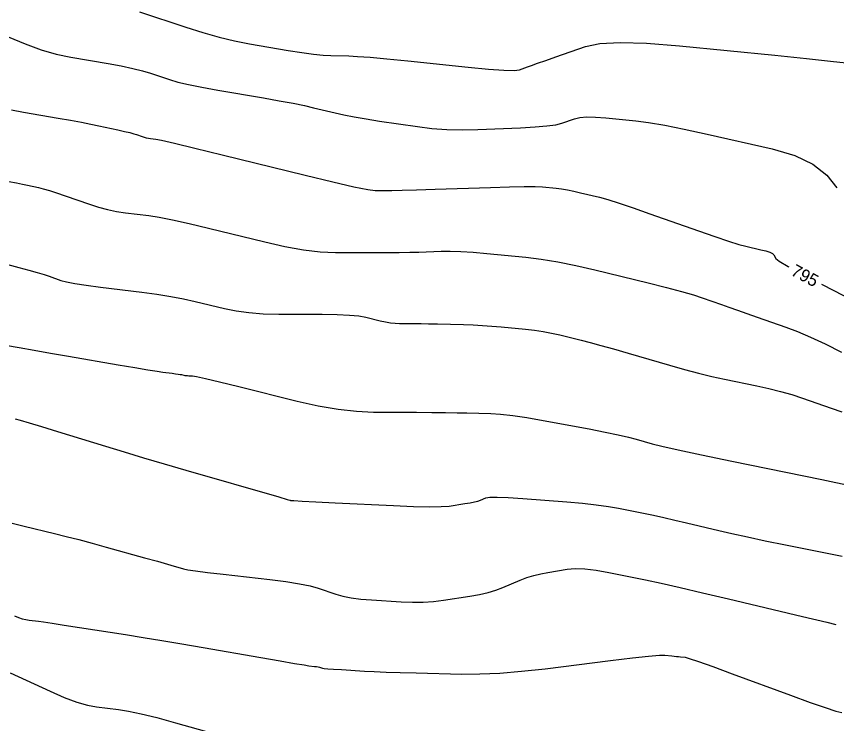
# Model space of a CAD drawing. Extents: x 2082232 to 2083549, y 592624 to 593832.
# Drawn here: x 2082281.15 to 2082327.71, y 593026.54 to 593066.69 of the extents above; entities that cross this region are included whole.
import ezdxf

# ---------------------------------------------------------------- set-up
doc = ezdxf.new("R2010")
doc.units = 0
doc.layers.add('DT_X_Contour_Major', color=7, linetype='Continuous')
doc.layers.add('DT_X_Contour_Minor', color=7, linetype='Continuous')

msp = doc.modelspace()

# ---------------------------------------------------------------- linework, layer by layer
at = {"layer": 'DT_X_Contour_Major'}
for points in [[(2082280.863, 593061.384), (2082281.552, 593061.256), (2082283.525, 593060.92), (2082284.223, 593060.799), (2082284.839, 593060.687), (2082285.371, 593060.584), (2082285.82, 593060.49), (2082286.908, 593060.251), (2082287.279, 593060.167), (2082287.579, 593060.095), (2082287.807, 593060.035), (2082287.963, 593059.987), (2082288.284, 593059.876), (2082288.404, 593059.837), (2082288.522, 593059.806), (2082288.64, 593059.781), (2082288.756, 593059.764), (2082289.064, 593059.726), (2082289.386, 593059.66), (2082290.121, 593059.488), (2082291.268, 593059.212), (2082292.827, 593058.83), (2082297.536, 593057.673), (2082299.109, 593057.293), (2082300.297, 593057.021), (2082301.1, 593056.858), (2082301.518, 593056.803), (2082302.119, 593056.801), (2082302.463, 593056.805), (2082303.045, 593056.82), (2082303.866, 593056.845), (2082304.924, 593056.881), (2082308.065, 593056.989), (2082309.132, 593057.021), (2082309.978, 593057.036), (2082310.603, 593057.034), (2082311.007, 593057.014), (2082311.79, 593056.939), (2082312.097, 593056.902), (2082312.431, 593056.847), (2082312.791, 593056.775), (2082313.177, 593056.686), (2082314.244, 593056.423), (2082314.723, 593056.291), (2082315.36, 593056.092), (2082316.155, 593055.827), (2082317.108, 593055.494), (2082319.861, 593054.519), (2082320.804, 593054.19), (2082321.569, 593053.934), (2082322.156, 593053.751), (2082322.564, 593053.642), (2082323.416, 593053.449), (2082323.7, 593053.376), (2082323.916, 593053.301), (2082324.063, 593053.226), (2082324.14, 593053.149), (2082324.255, 593052.941), (2082324.454, 593052.79), (2082324.966, 593052.491), (2082325.005, 593052.47)], [(2082326.86, 593051.486), (2082326.926, 593051.451), (2082330.373, 593049.672)], [(2082280.911, 593037.923), (2082281.594, 593037.745), (2082283.312, 593037.331), (2082283.979, 593037.167), (2082284.689, 593036.984), (2082285.444, 593036.784), (2082286.242, 593036.565), (2082288.429, 593035.958), (2082289.162, 593035.754), (2082289.721, 593035.597), (2082290.105, 593035.488), (2082290.315, 593035.426), (2082290.642, 593035.324), (2082290.874, 593035.276), (2082291.324, 593035.209), (2082291.992, 593035.124), (2082292.878, 593035.019), (2082295.532, 593034.716), (2082296.449, 593034.601), (2082297.212, 593034.482), (2082297.82, 593034.36), (2082298.274, 593034.235), (2082299.276, 593033.895), (2082299.685, 593033.779), (2082300.159, 593033.685), (2082300.698, 593033.612), (2082301.302, 593033.561), (2082302.999, 593033.455), (2082303.627, 593033.431), (2082304.235, 593033.439), (2082304.825, 593033.477), (2082305.395, 593033.547), (2082306.892, 593033.776), (2082307.429, 593033.871), (2082307.92, 593033.983), (2082308.363, 593034.114), (2082308.759, 593034.262), (2082309.753, 593034.681), (2082310.131, 593034.827), (2082310.517, 593034.95), (2082310.913, 593035.05), (2082311.318, 593035.127), (2082312.409, 593035.302), (2082312.865, 593035.34), (2082313.413, 593035.321), (2082314.054, 593035.247), (2082314.787, 593035.117), (2082316.866, 593034.695), (2082317.745, 593034.509), (2082318.823, 593034.269), (2082320.099, 593033.974), (2082321.575, 593033.625), (2082325.775, 593032.621), (2082327.156, 593032.291), (2082327.671, 593032.167)]]:
    msp.add_lwpolyline(points, dxfattribs=at)
at = {"layer": 'DT_X_Contour_Minor'}
for points in [[(2082288.139, 593066.96), (2082290.764, 593066.079), (2082291.729, 593065.773), (2082292.653, 593065.513), (2082293.537, 593065.301), (2082294.381, 593065.137), (2082296.579, 593064.76), (2082297.348, 593064.636), (2082298.007, 593064.546), (2082298.556, 593064.489), (2082298.994, 593064.466), (2082300.016, 593064.45), (2082300.512, 593064.427), (2082301.235, 593064.373), (2082302.184, 593064.287), (2082303.36, 593064.168), (2082306.797, 593063.808), (2082307.946, 593063.698), (2082308.815, 593063.637), (2082309.404, 593063.626), (2082309.714, 593063.665), (2082310.166, 593063.833), (2082310.394, 593063.916), (2082310.736, 593064.038), (2082311.195, 593064.2), (2082311.768, 593064.401), (2082313.452, 593064.989), (2082314.259, 593065.157), (2082315.416, 593065.219), (2082316.923, 593065.175), (2082318.781, 593065.026), (2082324.202, 593064.485), (2082326.007, 593064.302), (2082327.354, 593064.158), (2082328.243, 593064.053)], [(2082280.681, 593065.537), (2082281.638, 593065.13), (2082282.549, 593064.801), (2082283.414, 593064.549), (2082284.232, 593064.375), (2082286.353, 593064.014), (2082287.1, 593063.879), (2082287.749, 593063.744), (2082288.3, 593063.608), (2082288.754, 593063.472), (2082289.834, 593063.11), (2082290.309, 593062.97), (2082290.926, 593062.823), (2082291.684, 593062.669), (2082292.583, 593062.506), (2082295.169, 593062.064), (2082296.074, 593061.905), (2082296.852, 593061.759), (2082297.501, 593061.628), (2082298.022, 593061.511), (2082299.24, 593061.216), (2082299.741, 593061.104), (2082300.329, 593060.99), (2082301.004, 593060.874), (2082301.766, 593060.755), (2082303.915, 593060.435), (2082304.734, 593060.335), (2082305.578, 593060.274), (2082306.449, 593060.253), (2082307.345, 593060.271), (2082309.769, 593060.371), (2082310.597, 593060.415), (2082311.264, 593060.473), (2082311.771, 593060.545), (2082312.116, 593060.631), (2082312.821, 593060.877), (2082313.132, 593060.95), (2082313.535, 593060.984), (2082314.03, 593060.979), (2082314.617, 593060.936), (2082316.306, 593060.767), (2082317.034, 593060.673), (2082317.951, 593060.515), (2082319.057, 593060.294), (2082320.353, 593060.01), (2082324.059, 593059.169), (2082325.331, 593058.794), (2082326.364, 593058.3), (2082327.159, 593057.686), (2082327.717, 593056.953)], [(2082280.724, 593057.312), (2082281.149, 593057.237), (2082281.498, 593057.171), (2082281.772, 593057.114), (2082282.404, 593056.976), (2082282.676, 593056.907), (2082283.018, 593056.807), (2082283.431, 593056.674), (2082283.915, 593056.509), (2082285.3, 593056.027), (2082285.816, 593055.861), (2082286.328, 593055.725), (2082286.835, 593055.619), (2082287.337, 593055.543), (2082288.669, 593055.381), (2082289.255, 593055.291), (2082290.015, 593055.143), (2082290.949, 593054.937), (2082292.058, 593054.672), (2082295.244, 593053.889), (2082296.392, 593053.631), (2082297.444, 593053.447), (2082298.4, 593053.335), (2082299.261, 593053.296), (2082301.428, 593053.288), (2082302.199, 593053.288), (2082302.883, 593053.293), (2082303.483, 593053.302), (2082303.997, 593053.316), (2082305.253, 593053.359), (2082305.769, 593053.363), (2082306.375, 593053.344), (2082307.071, 593053.3), (2082307.856, 593053.232), (2082310.07, 593053.019), (2082310.937, 593052.915), (2082311.88, 593052.76), (2082312.898, 593052.556), (2082313.99, 593052.303), (2082317.004, 593051.56), (2082318.044, 593051.298), (2082318.903, 593051.07), (2082319.582, 593050.876), (2082320.079, 593050.714), (2082321.166, 593050.33), (2082321.598, 593050.177), (2082322.082, 593050.008), (2082322.616, 593049.822), (2082323.201, 593049.619), (2082324.829, 593049.056), (2082325.484, 593048.809), (2082326.229, 593048.489), (2082327.064, 593048.097), (2082327.99, 593047.632)], [(2082279.652, 593052.876), (2082281.292, 593052.436), (2082281.86, 593052.281), (2082282.336, 593052.146), (2082282.719, 593052.031), (2082283.01, 593051.936), (2082283.662, 593051.708), (2082283.987, 593051.62), (2082284.471, 593051.527), (2082285.114, 593051.427), (2082285.918, 593051.323), (2082288.273, 593051.036), (2082289.124, 593050.923), (2082289.91, 593050.798), (2082290.631, 593050.662), (2082291.288, 593050.514), (2082292.953, 593050.105), (2082293.615, 593049.97), (2082294.352, 593049.873), (2082295.164, 593049.814), (2082296.05, 593049.792), (2082298.514, 593049.783), (2082299.361, 593049.771), (2082300.054, 593049.74), (2082300.594, 593049.691), (2082300.981, 593049.623), (2082301.807, 593049.418), (2082302.107, 593049.351), (2082302.387, 593049.302), (2082302.647, 593049.273), (2082302.887, 593049.262), (2082303.5, 593049.259), (2082303.77, 593049.256), (2082304.12, 593049.25), (2082304.55, 593049.242), (2082305.06, 593049.23), (2082306.527, 593049.195), (2082307.073, 593049.178), (2082307.611, 593049.151), (2082308.141, 593049.115), (2082308.663, 593049.069), (2082310.045, 593048.937), (2082310.556, 593048.879), (2082311.051, 593048.806), (2082311.53, 593048.717), (2082311.993, 593048.613), (2082313.207, 593048.313), (2082313.715, 593048.183), (2082314.329, 593048.017), (2082315.049, 593047.815), (2082315.873, 593047.577), (2082318.214, 593046.894), (2082319.068, 593046.652), (2082319.875, 593046.439), (2082320.634, 593046.255), (2082321.347, 593046.099), (2082323.184, 593045.722), (2082323.863, 593045.572), (2082324.522, 593045.404), (2082325.162, 593045.22), (2082325.781, 593045.018), (2082327.408, 593044.455), (2082328.006, 593044.238)], [(2082280.534, 593048.021), (2082281.304, 593047.887), (2082282.157, 593047.739), (2082283.092, 593047.577), (2082284.108, 593047.401), (2082286.927, 593046.915), (2082287.878, 593046.752), (2082288.616, 593046.628), (2082289.141, 593046.544), (2082289.453, 593046.499), (2082290, 593046.433), (2082290.187, 593046.409), (2082290.335, 593046.389), (2082290.446, 593046.371), (2082290.519, 593046.356), (2082290.662, 593046.321), (2082290.719, 593046.31), (2082290.783, 593046.301), (2082290.853, 593046.296), (2082290.929, 593046.294), (2082291.141, 593046.293), (2082291.366, 593046.255), (2082291.881, 593046.139), (2082292.686, 593045.946), (2082293.781, 593045.677), (2082297.088, 593044.855), (2082298.288, 593044.585), (2082299.409, 593044.391), (2082300.45, 593044.272), (2082301.411, 593044.23), (2082303.867, 593044.217), (2082304.736, 593044.211), (2082305.502, 593044.203), (2082306.164, 593044.194), (2082306.721, 593044.183), (2082308.071, 593044.151), (2082308.636, 593044.117), (2082309.321, 593044.041), (2082310.125, 593043.921), (2082311.048, 593043.759), (2082313.669, 593043.268), (2082314.572, 593043.095), (2082315.316, 593042.942), (2082315.9, 593042.81), (2082316.326, 593042.699), (2082317.247, 593042.43), (2082317.789, 593042.293), (2082318.723, 593042.082), (2082320.048, 593041.799), (2082321.766, 593041.443), (2082326.868, 593040.395), (2082328.552, 593040.048)], [(2082281.086, 593043.84), (2082281.371, 593043.763), (2082281.867, 593043.618), (2082282.572, 593043.406), (2082283.487, 593043.126), (2082286.207, 593042.291), (2082287.258, 593041.972), (2082288.369, 593041.639), (2082289.541, 593041.293), (2082290.774, 593040.934), (2082296.041, 593039.41), (2082296.517, 593039.272), (2082296.679, 593039.225), (2082296.691, 593039.221), (2082296.696, 593039.22), (2082296.7, 593039.219), (2082296.704, 593039.218), (2082296.707, 593039.217), (2082296.717, 593039.216), (2082296.72, 593039.216), (2082296.724, 593039.215), (2082296.729, 593039.214), (2082296.733, 593039.212), (2082296.746, 593039.208), (2082296.906, 593039.199), (2082297.376, 593039.174), (2082298.155, 593039.135), (2082299.244, 593039.081), (2082302.562, 593038.916), (2082303.692, 593038.869), (2082304.593, 593038.849), (2082305.267, 593038.858), (2082305.713, 593038.894), (2082306.596, 593039.029), (2082306.901, 593039.08), (2082307.151, 593039.13), (2082307.348, 593039.179), (2082307.491, 593039.228), (2082307.799, 593039.358), (2082308.017, 593039.392), (2082308.44, 593039.396), (2082309.069, 593039.371), (2082309.902, 593039.315), (2082312.398, 593039.128), (2082313.284, 593039.053), (2082314.068, 593038.969), (2082314.752, 593038.875), (2082315.335, 593038.771), (2082316.755, 593038.483), (2082317.306, 593038.368), (2082317.896, 593038.239), (2082318.523, 593038.096), (2082319.189, 593037.94), (2082321.014, 593037.503), (2082321.764, 593037.33), (2082322.645, 593037.137), (2082323.657, 593036.924), (2082324.801, 593036.692), (2082328.025, 593036.047)], [(2082281.044, 593032.66), (2082281.261, 593032.569), (2082281.471, 593032.498), (2082281.676, 593032.446), (2082281.875, 593032.413), (2082282.397, 593032.353), (2082282.69, 593032.314), (2082283.178, 593032.242), (2082283.861, 593032.138), (2082284.738, 593032), (2082287.335, 593031.59), (2082288.342, 593031.429), (2082289.412, 593031.252), (2082290.547, 593031.061), (2082291.747, 593030.855), (2082295.03, 593030.285), (2082296.123, 593030.096), (2082296.939, 593029.957), (2082297.479, 593029.868), (2082297.741, 593029.829), (2082298.072, 593029.791), (2082298.186, 593029.777), (2082298.28, 593029.762), (2082298.353, 593029.748), (2082298.406, 593029.733), (2082298.521, 593029.695), (2082298.62, 593029.678), (2082298.832, 593029.657), (2082299.157, 593029.633), (2082299.594, 593029.604), (2082300.91, 593029.522), (2082301.464, 593029.492), (2082302.137, 593029.464), (2082302.93, 593029.439), (2082303.843, 593029.415), (2082306.438, 593029.356), (2082307.463, 593029.358), (2082308.593, 593029.409), (2082309.827, 593029.509), (2082311.167, 593029.657), (2082314.878, 593030.118), (2082316.114, 593030.267), (2082317.04, 593030.369), (2082317.655, 593030.424), (2082317.959, 593030.431), (2082318.355, 593030.388), (2082318.497, 593030.373), (2082318.626, 593030.359), (2082318.743, 593030.347), (2082318.847, 593030.337), (2082319.108, 593030.311), (2082319.348, 593030.245), (2082319.875, 593030.067), (2082320.687, 593029.777), (2082321.786, 593029.375), (2082325.096, 593028.151), (2082326.209, 593027.746), (2082327.063, 593027.446), (2082327.659, 593027.253), (2082327.997, 593027.167)], [(2082280.788, 593029.425), (2082283.06, 593028.38), (2082283.864, 593028.03), (2082284.572, 593027.765), (2082285.184, 593027.584), (2082285.701, 593027.488), (2082286.951, 593027.343), (2082287.505, 593027.255), (2082288.226, 593027.1), (2082289.116, 593026.878), (2082290.175, 593026.589), (2082293.223, 593025.729)]]:
    msp.add_lwpolyline(points, dxfattribs=at)

# ---------------------------------------------------------------- texts
at = {"layer": 'DT_X_Contour_Major'}
msp.add_text('795', height=0.7, rotation=332.0518, dxfattribs=at).set_placement((2082325.061, 593052.036))

doc.saveas('drawing.dxf')
